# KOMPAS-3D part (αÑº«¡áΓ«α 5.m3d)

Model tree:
1. Эскиз:1
2. Операция выдавливания:36
     Толщина стенки 1 = 2; Толщина стенки 2 = 6; Расстояние 1 = 1; Расстояние 2 = 3
3. Эскиз:38
4. Операция выдавливания:40
     Толщина стенки 1 = 2; Толщина стенки 2 = 6; Расстояние 1 = 5; Расстояние 2 = 3
5. Эскиз:39
6. Операция выдавливания:41
     Толщина стенки 1 = 2; Толщина стенки 2 = 6; Расстояние 1 = 1; Расстояние 2 = 3
7. Эскиз:40
8. Операция выдавливания:42
     Толщина стенки 1 = 2; Толщина стенки 2 = 2.5; Расстояние 1 = 50; Расстояние 2 = 3
9. Эскиз:41
10. Вырезать элемент выдавливания:4
     Толщина стенки 2 = 1.5; Расстояние 1 = 40
11. Эскиз:42
12. Операция выдавливания:43
     Толщина стенки 1 = 2; Толщина стенки 2 = 2.5; Расстояние 1 = 50; Расстояние 2 = 3
13. Эскиз:43
14. Вырезать элемент выдавливания:5
     Толщина стенки 2 = 1.5; Расстояние 1 = 40
15. Эскиз:44
16. Операция выдавливания:44
     Толщина стенки 1 = 2; Толщина стенки 2 = 2.5; Расстояние 1 = 10; Расстояние 2 = 3
17. Эскиз:45
18. Эскиз:46
19. Операция выдавливания:47
     Толщина стенки 1 = 2; Толщина стенки 2 = 6; Расстояние 1 = 1; Расстояние 2 = 3
20. Эскиз:47
21. Операция выдавливания:48
     Толщина стенки 1 = 2; Толщина стенки 2 = 6; Расстояние 1 = 5; Расстояние 2 = 3
22. Эскиз:48
23. Операция выдавливания:49
     Толщина стенки 1 = 2; Толщина стенки 2 = 6; Расстояние 1 = 1; Расстояние 2 = 3
24. Эскиз:49
25. Вырезать элемент выдавливания:6
     Толщина стенки 2 = 1.5; Расстояние 1 = 22
26. Эскиз:50
27. Вырезать элемент выдавливания:7
     Толщина стенки 2 = 1.5; Расстояние 1 = 1
28. Эскиз:51
29. Вырезать элемент выдавливания:8
     Толщина стенки 2 = 1.5; Расстояние 1 = 151
30. Эскиз:53
31. Операция выдавливания:51
     Толщина стенки 1 = 7; Расстояние 1 = 10; Расстояние 2 = 0.4
